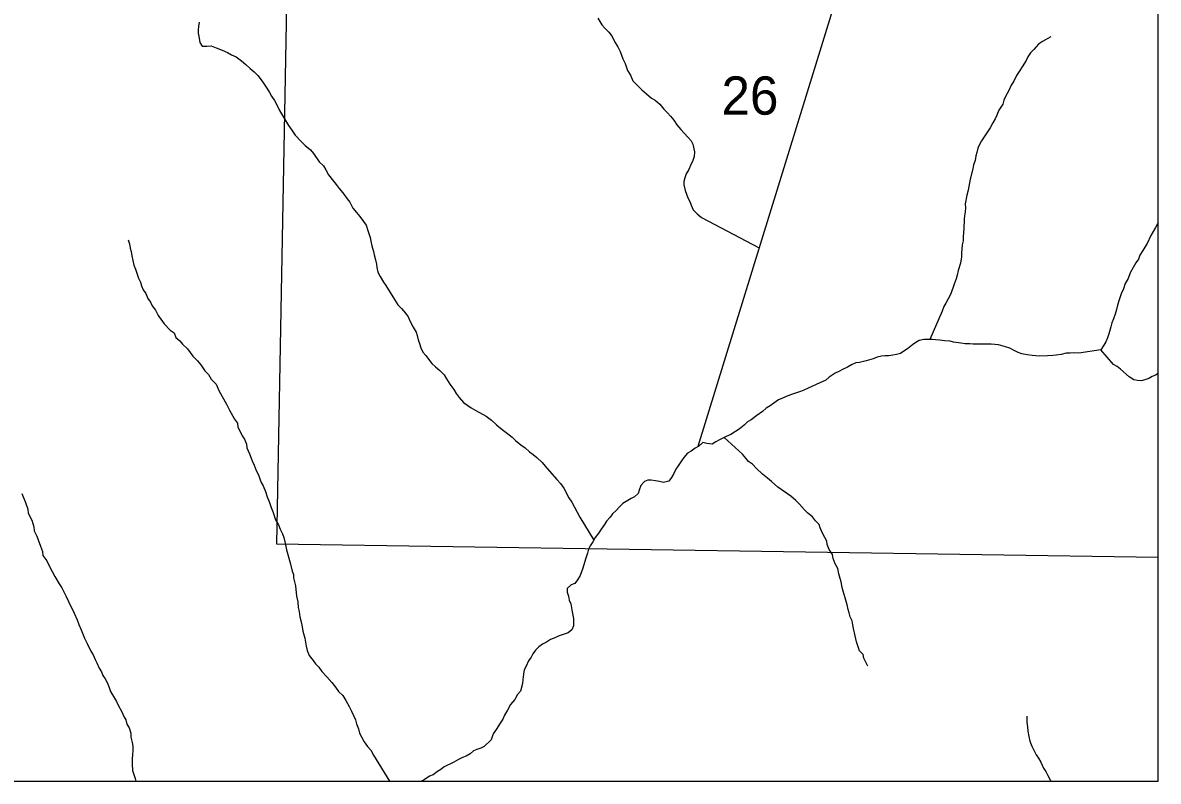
# Model space of a CAD drawing. Extents: x -10 to 158, y 8 to 33.
# Drawn here: x 30.159 to 31.4, y 14.1 to 14.93 of the extents above; entities that cross this region are included whole.
import ezdxf

# ---------------------------------------------------------------- set-up
doc = ezdxf.new("R2010")
doc.units = 0
for name, color, linetype in [('GM_X_Corporation', 7, 'Continuous'), ('GM_X_Minor_River', 7, 'Continuous'), ('GM_X_Section_Text', 7, 'Continuous')]:
    doc.layers.add(name, color=color, linetype=linetype)

msp = doc.modelspace()

# ---------------------------------------------------------------- linework, layer by layer
at = {"layer": 'GM_X_Corporation'}
for points in [[(29.6227, 14.1), (31.4, 14.1), (31.4, 20.9), (29.731, 20.9), (29.7244, 20.2649), (29.6982, 19.2496), (29.6981, 19.2461), (29.6974, 19.2018), (29.6957, 19.0991), (29.6992, 18.9556), (29.697, 18.9465), (29.6949, 18.8465), (29.6846, 18.5133), (29.6817, 18.3306), (29.6804, 18.2238), (29.6572, 17.4131), (29.6504, 16.6563), (29.6434, 16.3848), (29.6318, 15.4937)], [(31.4, 14.3451), (31.4, 15.3662), (30.4552, 15.381), (30.4363, 14.3597)]]:
    msp.add_lwpolyline(points, close=True, dxfattribs=at)
at = {"layer": 'GM_X_Minor_River'}
for points in [[(31.0928, 15.0717), (31.0872, 15.0666), (31.0831, 15.0624), (31.0787, 15.0566), (31.075, 15.0516), (31.0717, 15.0459), (31.0698, 15.0421), (31.068, 15.0363), (31.0659, 15.031), (31.0652, 15.0257), (31.0642, 15.0192), (31.0639, 15.0154), (31.0636, 15.0113), (31.0633, 15.0063), (30.8969, 14.4661)], [(30.7875, 14.9344), (30.7918, 14.9272), (30.7953, 14.9235), (30.7995, 14.9194), (30.803, 14.9145), (30.8062, 14.9082), (30.8093, 14.9033), (30.812, 14.898), (30.8148, 14.8901), (30.8172, 14.8848), (30.8199, 14.8773), (30.8231, 14.8721), (30.8258, 14.866), (30.83, 14.8616), (30.8354, 14.856), (30.8408, 14.8519), (30.8462, 14.8471), (30.85, 14.8449), (30.8554, 14.8404), (30.8596, 14.8352), (30.8635, 14.8311), (30.867, 14.8273), (30.8704, 14.8229), (30.8739, 14.818), (30.8782, 14.8128), (30.8817, 14.8087), (30.8863, 14.8042), (30.8894, 14.8004), (30.8913, 14.7967), (30.893, 14.7884), (30.8927, 14.7834), (30.8913, 14.7789), (30.8887, 14.7735), (30.8869, 14.7689), (30.8839, 14.7643), (30.8825, 14.7601), (30.8814, 14.756), (30.8815, 14.7522), (30.8831, 14.7461), (30.8843, 14.742), (30.8859, 14.7382), (30.8879, 14.7341), (30.8895, 14.7299), (30.8918, 14.7251), (30.8961, 14.7206), (30.9007, 14.7165), (30.9638, 14.6833)], [(30.3517, 14.9301), (30.351, 14.9255), (30.3507, 14.9218), (30.3508, 14.918), (30.3516, 14.9127), (30.3525, 14.9081), (30.3552, 14.904), (30.3601, 14.9041), (30.365, 14.9042), (30.3704, 14.902), (30.3768, 14.8995), (30.3826, 14.8969), (30.3871, 14.8943), (30.3921, 14.8922), (30.3982, 14.8877), (30.4028, 14.884), (30.4074, 14.8795), (30.4117, 14.8758), (30.4159, 14.8717), (30.4194, 14.8672), (30.4229, 14.8624), (30.4256, 14.8579), (30.4287, 14.8534), (30.4307, 14.8492), (30.4342, 14.8444), (30.4373, 14.8384), (30.4397, 14.8335), (30.4463, 14.8226), (30.4494, 14.817), (30.4529, 14.8121), (30.4568, 14.8065), (30.4633, 14.7998), (30.4676, 14.7953), (30.4733, 14.7905), (30.4768, 14.7867), (30.483, 14.7774), (30.4876, 14.7729), (30.4903, 14.7688), (30.4931, 14.7631), (30.4985, 14.7564), (30.5016, 14.7527), (30.5047, 14.7482), (30.5086, 14.7437), (30.5136, 14.737), (30.5163, 14.7332), (30.5198, 14.7268), (30.5237, 14.722), (30.5272, 14.7175), (30.5314, 14.7123), (30.5342, 14.7081), (30.5361, 14.7025), (30.5386, 14.6946), (30.5394, 14.6908), (30.5406, 14.6855), (30.5422, 14.6795), (30.543, 14.6757)], [(31.2824, 14.9143), (31.2734, 14.9092), (31.269, 14.9061), (31.2638, 14.9003), (31.2604, 14.8965), (31.2575, 14.8922), (31.2556, 14.8884), (31.2512, 14.8815), (31.2479, 14.8761), (31.245, 14.8719), (31.242, 14.8658), (31.2391, 14.8612), (31.2365, 14.8555), (31.2329, 14.849), (31.2311, 14.8448), (31.23, 14.8406), (31.2259, 14.8341), (31.2234, 14.8283), (31.2216, 14.8245), (31.219, 14.8199), (31.2164, 14.8146), (31.2068, 14.8004), (31.2046, 14.7965), (31.2028, 14.7923), (31.2018, 14.7878), (31.2007, 14.784), (31.1997, 14.779), (31.1982, 14.7741), (31.1972, 14.7699), (31.1943, 14.7584), (31.1923, 14.7463), (31.1909, 14.7409), (31.1891, 14.7314), (31.1892, 14.7273), (31.1889, 14.7227), (31.1882, 14.7185), (31.1879, 14.7147), (31.1873, 14.7041), (31.187, 14.7003), (31.1867, 14.6954), (31.1868, 14.6912), (31.1857, 14.6866), (31.1851, 14.6775), (31.1848, 14.6737), (31.1838, 14.6665), (31.1813, 14.6585), (31.1803, 14.6536), (31.1792, 14.6494), (31.177, 14.6437), (31.1734, 14.633), (31.1705, 14.6276), (31.1679, 14.623), (31.1657, 14.6192), (31.1639, 14.6142), (31.1505, 14.5831)], [(31.4, 14.7111), (31.3991, 14.7098), (31.3969, 14.7055), (31.3918, 14.6967), (31.3878, 14.6883), (31.3852, 14.6841), (31.383, 14.6803), (31.38, 14.6753), (31.3782, 14.6711), (31.3753, 14.6669), (31.3727, 14.6619), (31.3694, 14.6562), (31.3672, 14.6497), (31.3639, 14.6443), (31.3618, 14.6386), (31.3596, 14.6332), (31.3571, 14.6267), (31.3553, 14.6207), (31.3542, 14.6161), (31.3528, 14.6108), (31.351, 14.6058), (31.3492, 14.6012), (31.3481, 14.597), (31.346, 14.5894), (31.3445, 14.5848), (31.3427, 14.5806), (31.3405, 14.5768), (31.3372, 14.5718)], [(30.2741, 14.6922), (30.2757, 14.6877), (30.2765, 14.6831), (30.2773, 14.6794), (30.2782, 14.6748), (30.2794, 14.6696), (30.2802, 14.6646), (30.2822, 14.6601), (30.2854, 14.6503), (30.2878, 14.6458), (30.2886, 14.6417), (30.2906, 14.6375), (30.2933, 14.6334), (30.2956, 14.6278), (30.2987, 14.624), (30.3003, 14.6199), (30.3042, 14.6154), (30.3069, 14.6094), (30.3097, 14.6053), (30.3135, 14.6004), (30.3201, 14.5933), (30.3243, 14.5904), (30.3263, 14.5855), (30.3305, 14.5817), (30.3336, 14.578), (30.339, 14.5728), (30.3448, 14.5649), (30.3498, 14.5597), (30.3537, 14.5556), (30.3579, 14.5489), (30.3618, 14.5448), (30.3649, 14.5399), (30.3703, 14.5343), (30.3734, 14.5275), (30.377, 14.5208), (30.3816, 14.5125), (30.3848, 14.5058), (30.3903, 14.496), (30.3937, 14.4915), (30.3942, 14.4877), (30.3989, 14.4779), (30.4012, 14.4742), (30.4036, 14.4686), (30.404, 14.4648), (30.4068, 14.458), (30.4096, 14.4505), (30.4119, 14.4456), (30.4139, 14.4399), (30.4163, 14.4358), (30.4195, 14.4268), (30.4218, 14.423), (30.4242, 14.417), (30.4262, 14.411), (30.4285, 14.4049), (30.4305, 14.3993), (30.4325, 14.394), (30.4353, 14.3861), (30.4384, 14.3805), (30.4404, 14.3756), (30.4428, 14.3707), (30.4443, 14.3665), (30.4456, 14.3605), (30.4472, 14.3533), (30.4513, 14.339), (30.4533, 14.3299), (30.4549, 14.3262), (30.4549, 14.3224), (30.457, 14.3137), (30.4583, 14.3023), (30.4596, 14.2963), (30.46, 14.2902), (30.4609, 14.2857), (30.4617, 14.2797), (30.4629, 14.2759), (30.4642, 14.2691), (30.465, 14.2642), (30.4671, 14.2566), (30.4687, 14.2476), (30.4699, 14.243), (30.4719, 14.2374), (30.4762, 14.2322), (30.4789, 14.2284), (30.4824, 14.2247), (30.4859, 14.2202), (30.4913, 14.2142), (30.4967, 14.2079), (30.5009, 14.203), (30.504, 14.1981), (30.5086, 14.1937), (30.5121, 14.1884), (30.5157, 14.1817), (30.5184, 14.1768), (30.5208, 14.1712), (30.5227, 14.1674), (30.5236, 14.1629), (30.5259, 14.1572), (30.5271, 14.1527), (30.5291, 14.1486), (30.5322, 14.1433), (30.5357, 14.1381), (30.5392, 14.1339)], [(30.543, 14.6757), (30.5443, 14.6704), (30.5455, 14.6655), (30.5459, 14.6617), (30.5472, 14.6568), (30.5495, 14.6519), (30.5534, 14.6459), (30.5557, 14.6422), (30.5651, 14.6268), (30.569, 14.6212), (30.5728, 14.6171), (30.5771, 14.6119), (30.5802, 14.6081), (30.5825, 14.6029), (30.5857, 14.5968), (30.5888, 14.5912), (30.59, 14.5874), (30.5912, 14.5829), (30.5924, 14.5788), (30.594, 14.5739), (30.5963, 14.5694), (30.5994, 14.5656), (30.6025, 14.5615), (30.606, 14.557), (30.6102, 14.5533), (30.6149, 14.5492), (30.6195, 14.5444), (30.6222, 14.5403), (30.6257, 14.5342), (30.63, 14.5283), (30.6327, 14.5241), (30.6358, 14.5196), (30.6408, 14.5144), (30.6454, 14.5111), (30.6492, 14.5085), (30.6542, 14.5056), (30.6653, 14.4993), (30.6714, 14.4949), (30.6768, 14.49), (30.6829, 14.4848), (30.6887, 14.4804), (30.6937, 14.4763), (30.6975, 14.4726), (30.7033, 14.4681), (30.7079, 14.4648), (30.7129, 14.4603), (30.7167, 14.4574), (30.7209, 14.454), (30.7267, 14.4485), (30.7298, 14.4447), (30.7348, 14.4391), (30.7425, 14.4302), (30.7468, 14.4257), (30.7503, 14.4204), (30.7558, 14.4099), (30.7592, 14.4054), (30.7679, 14.3889), (30.783, 14.3638)], [(31.4, 14.546), (31.3971, 14.5441), (31.3933, 14.5425), (31.3896, 14.5405), (31.3854, 14.5389), (31.3813, 14.5381), (31.3771, 14.5384), (31.3733, 14.5391), (31.368, 14.5424), (31.3588, 14.5506), (31.3549, 14.5535), (31.3511, 14.5558), (31.3372, 14.5718), (31.313, 14.5683), (31.3085, 14.5686), (31.3036, 14.5682), (31.2994, 14.5681), (31.2938, 14.5669), (31.2885, 14.566), (31.2847, 14.5656), (31.279, 14.5651), (31.27, 14.5649), (31.262, 14.5656), (31.2567, 14.5662), (31.251, 14.5676), (31.2468, 14.5691), (31.2418, 14.5713), (31.2376, 14.5735), (31.2331, 14.5753), (31.2255, 14.5774), (31.2175, 14.578), (31.2073, 14.5779), (31.2028, 14.5782), (31.1978, 14.5781), (31.194, 14.5784), (31.1891, 14.5783), (31.1842, 14.579), (31.1762, 14.5803), (31.1724, 14.5814), (31.1664, 14.5817), (31.1614, 14.5823), (31.1565, 14.5826), (31.1527, 14.583), (31.1474, 14.5832), (31.1436, 14.5832), (31.1387, 14.5819), (31.135, 14.58), (31.1313, 14.5773), (31.126, 14.573), (31.1219, 14.5703), (31.1182, 14.5679), (31.114, 14.5667), (31.1099, 14.5659), (31.1054, 14.5654), (31.1012, 14.5654), (31.0974, 14.5649), (31.0929, 14.5637), (31.0884, 14.5621), (31.0809, 14.5597), (31.0733, 14.558), (31.0695, 14.5576), (31.0647, 14.5556), (31.0605, 14.5529), (31.0549, 14.5505), (31.0508, 14.5482), (31.0467, 14.5462), (31.0403, 14.5419), (31.0366, 14.5388), (31.0261, 14.5341), (31.0212, 14.5317)], [(31.0212, 14.5317), (31.0174, 14.5298), (31.0125, 14.5278), (31.0088, 14.5262), (31.0001, 14.5234), (30.9952, 14.5214), (30.9892, 14.519), (30.9851, 14.5171), (30.9799, 14.5136), (30.9758, 14.5105), (30.9716, 14.5081), (30.9675, 14.5043), (30.9612, 14.5), (30.9552, 14.4953), (30.9511, 14.493), (30.9474, 14.4895), (30.9418, 14.4852), (30.938, 14.4825), (30.9328, 14.4794), (30.9279, 14.477), (30.9242, 14.4751), (30.9204, 14.4735), (30.9163, 14.4711), (30.9125, 14.4688), (30.9065, 14.4694), (30.9023, 14.4705), (30.8978, 14.4666), (30.8937, 14.4643), (30.8896, 14.4612), (30.8855, 14.4588), (30.8814, 14.4542), (30.8781, 14.4492), (30.8751, 14.445), (30.8729, 14.4412), (30.8707, 14.4366), (30.8681, 14.4324), (30.8652, 14.4282), (30.8591, 14.4269), (30.855, 14.428), (30.8504, 14.4287), (30.8459, 14.4293), (30.8421, 14.4293), (30.8383, 14.4277), (30.8346, 14.4234), (30.8328, 14.4185), (30.8317, 14.4147), (30.8276, 14.4112), (30.8239, 14.4092), (30.8149, 14.4038), (30.8112, 14.4003), (30.8075, 14.3961), (30.8034, 14.3926), (30.8008, 14.3887), (30.7971, 14.3845), (30.7949, 14.3807), (30.7912, 14.3757), (30.7886, 14.3718), (30.7845, 14.3665), (30.7819, 14.3619), (30.779, 14.3576), (30.7772, 14.3538), (30.7761, 14.3493), (30.7743, 14.3439), (30.7729, 14.3393), (30.7711, 14.3329), (30.7682, 14.3252), (30.7653, 14.3203), (30.7623, 14.3164), (30.7585, 14.3148), (30.7541, 14.311), (30.7541, 14.3068), (30.7554, 14.3023), (30.7562, 14.2981), (30.7578, 14.294), (30.7586, 14.2898), (30.7594, 14.2853), (30.7603, 14.2815), (30.7607, 14.2777), (30.7608, 14.2701), (30.759, 14.2656), (30.7549, 14.2625), (30.7508, 14.2609), (30.7451, 14.2589), (30.7403, 14.2569), (30.7357, 14.2549), (30.7313, 14.2522), (30.7271, 14.2498), (30.723, 14.2471), (30.7193, 14.2433), (30.7163, 14.2394), (30.7145, 14.2356), (30.7116, 14.2317), (30.709, 14.226), (30.7068, 14.2218), (30.7061, 14.2172), (30.7055, 14.2115), (30.7052, 14.207), (30.703, 14.1986), (30.6997, 14.1948), (30.6968, 14.1894), (30.6919, 14.184)], [(31.0825, 14.2258), (31.0782, 14.2348), (31.0773, 14.2386), (31.0735, 14.2427), (31.0703, 14.2525), (31.0687, 14.2589), (31.067, 14.2672), (31.0662, 14.271), (31.0653, 14.2755), (31.0634, 14.28), (31.0622, 14.2842), (31.061, 14.2879), (31.0598, 14.2928), (31.0577, 14.3008), (31.0557, 14.3079), (31.0545, 14.3121), (31.0533, 14.3181), (31.0524, 14.3219), (31.0508, 14.3268), (31.0496, 14.3328), (31.0469, 14.3377), (31.0445, 14.3437), (31.044, 14.3479), (31.0402, 14.3535), (31.0382, 14.3588), (31.0377, 14.3626), (31.0334, 14.3705), (31.0303, 14.3772), (31.0295, 14.381), (31.0252, 14.3847), (31.0221, 14.3892), (31.0171, 14.3933), (31.0133, 14.397), (31.0079, 14.403), (31.004, 14.4071), (30.9983, 14.4119), (30.9891, 14.4182), (30.9841, 14.4215), (30.9772, 14.4278), (30.973, 14.4316), (30.9676, 14.436), (30.9607, 14.442), (30.9564, 14.4468), (30.9522, 14.4498), (30.9491, 14.4535), (30.9456, 14.4576), (30.9414, 14.4613), (30.9257, 14.4758)], [(30.1578, 14.4146), (30.1618, 14.4048), (30.1645, 14.3976), (30.165, 14.3931), (30.1689, 14.3856), (30.1709, 14.3784), (30.1714, 14.3739), (30.1745, 14.3679), (30.1757, 14.3641), (30.1785, 14.3573), (30.1805, 14.3513), (30.1809, 14.3471), (30.1852, 14.3411), (30.1872, 14.337), (30.1911, 14.3295), (30.1942, 14.3239), (30.1989, 14.316), (30.2016, 14.3115), (30.2059, 14.3028), (30.2091, 14.2965), (30.215, 14.284), (30.2185, 14.2765), (30.2201, 14.2716), (30.2228, 14.2656), (30.2264, 14.2566), (30.2292, 14.2506), (30.2335, 14.2423), (30.2358, 14.2382), (30.2382, 14.2333), (30.2401, 14.2295), (30.2425, 14.2239), (30.2452, 14.2198), (30.2464, 14.2156), (30.2491, 14.2119), (30.2511, 14.2081), (30.2534, 14.2025), (30.255, 14.1983), (30.2582, 14.1927), (30.2613, 14.1874), (30.2632, 14.1833), (30.2672, 14.1758), (30.2695, 14.1709), (30.2715, 14.1671), (30.2727, 14.1626), (30.2754, 14.1585), (30.277, 14.1528), (30.2771, 14.1483), (30.2787, 14.1423), (30.2792, 14.1385), (30.2792, 14.1339), (30.2789, 14.129), (30.2786, 14.1248), (30.2787, 14.1188), (30.2789, 14.1119), (30.2804, 14.1074), (30.2817, 14.1029), (30.2825, 14.1)], [(30.6919, 14.184), (30.6886, 14.1779), (30.6853, 14.1725), (30.6835, 14.1679), (30.6806, 14.1637), (30.6765, 14.1568), (30.6732, 14.1518), (30.671, 14.1454), (30.6632, 14.138), (30.6595, 14.1361), (30.6553, 14.1349), (30.6516, 14.1333), (30.6479, 14.1302), (30.6437, 14.1274), (30.6396, 14.1259), (30.6351, 14.1239), (30.6302, 14.1211), (30.6197, 14.1157), (30.616, 14.1129), (30.6122, 14.1106), (30.6074, 14.1071), (30.6036, 14.1055), (30.5976, 14.1016), (30.5948, 14.1)], [(31.2564, 14.1712), (31.2565, 14.1648), (31.2569, 14.1595), (31.2574, 14.1549), (31.2586, 14.1489), (31.2595, 14.144), (31.2618, 14.1383), (31.2642, 14.1334), (31.2665, 14.1289), (31.2689, 14.1252), (31.2716, 14.1211), (31.2747, 14.1143), (31.2771, 14.1106), (31.2794, 14.1064), (31.2818, 14.1015), (31.2824, 14.1)], [(30.5392, 14.1339), (30.5423, 14.1287), (30.5597, 14.1)]]:
    msp.add_lwpolyline(points, dxfattribs=at)

# ---------------------------------------------------------------- texts
at = {"layer": 'GM_X_Section_Text'}
msp.add_text('26', height=0.04186, rotation=0, dxfattribs=at).set_placement((30.9226, 14.829))

doc.saveas('drawing.dxf')
